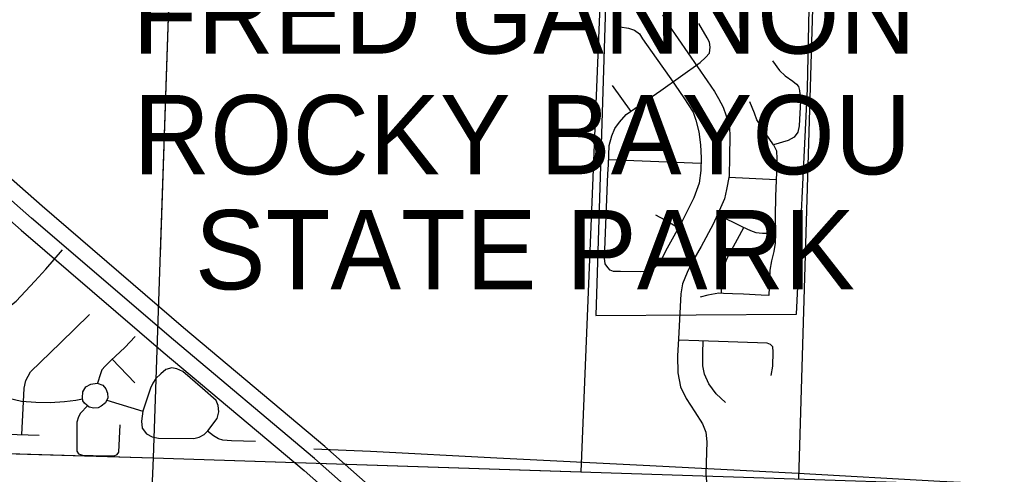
# Model space of a CAD drawing. Extents: x 1219626 to 1426462, y 456797 to 752399.
# Drawn here: x 1360454 to 1366612, y 546709 to 549577 of the extents above; entities that cross this region are included whole.
import ezdxf

# ---------------------------------------------------------------- set-up
doc = ezdxf.new("R2010")
doc.units = 0
for name, color, linetype in [('Local Roads Paved', 7, 'Continuous'), ('Masks', 7, 'Continuous'), ('Masks for Text', 7, 'Continuous'), ('Section Lines', 7, 'Continuous'), ('State Park', 7, 'Continuous'), ('State Park Text', 7, 'Continuous'), ('State Route Divided Highway Outline and Fill', 7, 'Continuous'), ('State Routes Highway Center Lines', 7, 'Continuous')]:
    doc.layers.add(name, color=color, linetype=linetype)

msp = doc.modelspace()

# ---------------------------------------------------------------- linework, layer by layer
at = {"layer": 'Local Roads Paved'}
for p, q in [((1364190.4, 549161), (1364306.7, 548997.8)), ((1364167.5, 548695.3), (1364749.7, 548671.8)), ((1365223.9, 548565.7), (1364925, 548580.7)), ((1361038.4, 547435.6), (1361179.9, 547285.4)), ((1361003.5, 547177.1), (1361232, 547106.8))]:
    msp.add_line(p, q, dxfattribs=at)
for points in [[(1364506.4, 549607.1), (1364545.4, 549542.9), (1364788.1, 549191), (1364834.1, 549124.2), (1364859.2, 549080), (1364888.7, 549024.5), (1364908.6, 548969.9), (1364916.4, 548940.4), (1364928.6, 548892.7), (1364932, 548845), (1364928.6, 548709.8), (1364926.8, 548591), (1364911.2, 548505.2), (1364897.4, 548447.1), (1364872.2, 548389), (1364827.1, 548285.9), (1364750, 548146.3), (1364697.1, 548050.9), (1364662.4, 547981.6), (1364633.8, 547911.4), (1364622.5, 547847.2), (1364607.8, 547563.7), (1364602.6, 547457.1), (1364604.3, 547350.4), (1364619.9, 547260.3), (1364655.5, 547187.5), (1364711, 547104.2), (1364758.7, 547027.1), (1364780.3, 546975.1), (1364787.3, 546915.2), (1364779.5, 546714.1), (1364784.7, 546663)], [(1364239.8, 549530.4), (1364291.8, 549523.4), (1364330, 549510.4), (1364362, 549486.1), (1364381.1, 549454.9), (1364466.9, 549333.6), (1364558.8, 549203.5), (1364642.1, 549083.9), (1364700.1, 548992.9), (1364717.5, 548942.6), (1364735.7, 548869.8), (1364747, 548786.5), (1364750.4, 548705.9), (1364748.7, 548624.4), (1364737.4, 548544.7), (1364704.5, 548452.8), (1364677.6, 548397.3), (1364630.8, 548305.4), (1364536.3, 548134.6), (1364487.7, 548041), (1364453.1, 548006.3), (1364416.6, 547989.8), (1364369.8, 547985.5), (1364243.3, 547988.1), (1364199, 547988.9), (1364177.4, 547997.6), (1364161.8, 548013.2), (1364146.2, 548037.5), (1364141.8, 548072.2), (1364162.6, 548604.5), (1364166.1, 548661.7), (1364171.3, 548783.9), (1364187.8, 548843.7), (1364206, 548890.6), (1364236.3, 548929.6), (1364277.9, 548977.3), (1364359.4, 549035.3), (1364496.4, 549129.8), (1364745.2, 549306.7), (1364779, 549337), (1364802.4, 549365.6), (1364808.5, 549402.1), (1364802.4, 549435), (1364788.6, 549461.9), (1364735.7, 549552.9)], [(1365200.4, 549316.2), (1365244.6, 549256.4), (1365280.1, 549221.7), (1365327.8, 549188.8), (1365352.1, 549169.7), (1365364.2, 549155.8), (1365371.1, 549130.7), (1365377.2, 549063.9), (1365368.5, 548906.2), (1365359.9, 548866.3), (1365337.3, 548835.9), (1365299.2, 548815.1), (1365206.4, 548787.4), (1365156.1, 548860.2), (1365101.5, 548945.2), (1365086.8, 548986.8), (1365057.3, 549058.7)], [(1365206, 548788), (1365226.4, 548749.2), (1365228.1, 548699), (1365226.4, 548614), (1365218.6, 548462.3), (1365217.7, 548337.5), (1365219.4, 548226.5), (1365217.7, 548167.5), (1365208.2, 548115.5), (1365193.4, 548055.7), (1365184.8, 547996.7), (1365182.2, 547940.4), (1365177.8, 547837.2), (1365130.1, 547838.1), (1365017.4, 547845), (1364948.9, 547847.6), (1364891.7, 547850.2), (1364861.4, 547852), (1364792.9, 547839), (1364744.4, 547826)], [(1362310, 546871), (1362666.3, 546856.3), (1363462.2, 546813.8), (1364427.1, 546764.4), (1365361.6, 546716.7), (1366256.3, 546667.3), (1367164.8, 546622.2), (1367542, 546604.9), (1367765.6, 546603.1), (1367974.6, 546610.1), (1368079.5, 546616.2), (1368255.4, 546629.2), (1368565.8, 546674.2), (1368850.2, 546726.3), (1368988.9, 546756.6), (1369250.7, 546826), (1369484.8, 546898.8), (1369633.9, 546949.1), (1369932.1, 547072.2), (1370656.9, 547398.1), (1371339.1, 547704.2), (1372184.4, 548082.1), (1372487, 548217.4), (1372702.8, 548311)], [(1364607.1, 548262.6), (1364523.3, 548312.3), (1364465, 548342.6)], [(1364854.1, 548347.6), (1365010.5, 548269), (1365062.5, 548247.3), (1365096.3, 548235.2), (1365137.1, 548230), (1365219.4, 548230)], [(1364878.4, 547851), (1364880.5, 547937.8), (1364889.1, 547991.5), (1364899.5, 548034), (1364916.9, 548075.6), (1364979.3, 548191.8), (1365020.1, 548265)], [(1359142.5, 546467.9), (1359161.1, 546551.3), (1359165.4, 546658), (1359168, 546723.9), (1359177.5, 546812.3), (1359186.2, 546850.4), (1359207, 546905.9), (1359256.4, 546970.9), (1359396.9, 547106.2), (1359491.4, 547198.1), (1359632.7, 547335.1), (1359704.6, 547405.3), (1359771.4, 547463.4), (1359819.1, 547499.8), (1359891.9, 547546.6), (1360097.4, 547621.1), (1360200.5, 547655), (1360297.6, 547702.6), (1360371.3, 547752.9), (1360432, 547802.3), (1360550.8, 547928), (1360620.1, 548003.5), (1360724.2, 548125.7)], [(1360467.4, 546959.9), (1360476.6, 547125.3), (1360482.9, 547252.5), (1360493.3, 547301), (1360521.9, 547355.6), (1360711.8, 547537.7), (1360893.9, 547716.3)], [(1361183.4, 547579.3), (1361116.7, 547510), (1361030, 547427.6), (1360993.6, 547391.2), (1360973.6, 547368.7), (1360963.2, 547342.6), (1360945, 547283.7)], [(1365191.4, 547333), (1365201.7, 547392.1), (1365205.1, 547482.2), (1365201.7, 547512.6), (1365187.8, 547527.3), (1365167.8, 547536), (1364735.2, 547550.7), (1364607.4, 547556.2)], [(1364904.7, 547161.5), (1364844.5, 547216.9), (1364798.5, 547280.2), (1364771.7, 547340.9), (1364760.4, 547392.9), (1364760.4, 547475.3), (1364763.4, 547549.7)], [(1361640.3, 546982.9), (1361700.1, 547061.8), (1361710.5, 547102.5), (1361706.2, 547142.4), (1361693.2, 547174.5), (1361607.3, 547249.9), (1361483.4, 547358.2), (1361444.4, 547375.6), (1361414, 547379.9), (1361375.9, 547370.4), (1361344.7, 547343.5), (1361313.5, 547314), (1361293.5, 547283.7), (1361278.8, 547252.5), (1361232, 547106.8)], [(1360386, 547190.3), (1360466.7, 547171.2), (1360556.8, 547165.1), (1360647, 547163.4), (1360738, 547167.7), (1360809.1, 547178.1), (1360851.6, 547184.5)], [(1360882, 547141.4), (1360838.4, 547095.6), (1360825.4, 547072.2), (1360815.8, 547037.5), (1360815, 546854.6), (1360825.4, 546838.1), (1360850.5, 546831.2), (1360917.3, 546827.7), (1361049.9, 546826), (1361069, 546835.5), (1361079.4, 546849.4), (1361087.2, 547021)], [(1361232, 547106.8), (1361223.3, 547045.3), (1361227.6, 547001.1), (1361254.5, 546964.7), (1361289.2, 546945.6), (1361329.1, 546937.8), (1361552.7, 546935.2), (1361585.7, 546943.9), (1361617.7, 546961.2), (1361640.3, 546982.9)], [(1360299.4, 547002.2), (1360342.7, 546970.1), (1360369.6, 546963.1), (1360576.8, 546956.2)], [(1361942, 546916.1), (1361789.4, 546921.3), (1361735.6, 546925.6), (1361707.9, 546932.6), (1361676.7, 546951.7), (1361639, 546981.6)]]:
    msp.add_lwpolyline(points, dxfattribs=at)
msp.add_lwpolyline([(1360904.3, 547278.5), (1360942.4, 547284.6), (1360977.9, 547272.4), (1360998.8, 547249), (1361007.4, 547220.4), (1361010, 547192.7), (1360996.2, 547159.7), (1360968.4, 547138.9), (1360948.5, 547128.5), (1360922.5, 547126.8), (1360892.1, 547132.8), (1360863.5, 547157.1), (1360853.1, 547173.6), (1360850.5, 547192.7), (1360853.1, 547229.9), (1360872.2, 547261.2)], close=True, dxfattribs=at)
at = {"layer": 'Masks'}
msp.add_line((1361404.8, 549976.7), (1361340.2, 548094.8), dxfattribs=at)
at = {"layer": 'Masks for Text'}
msp.add_lwpolyline([(1364157.2, 549934), (1364086.3, 547711.9), (1365351.2, 547720.3), (1365422.2, 549140.4), (1365438.9, 549950.7), (1364232.4, 549988.3)], close=True, dxfattribs=at)
at = {"layer": 'Section Lines'}
for p, q in [((1361423.7, 550528.5), (1361296.2, 546813.7)), ((1355893.4, 546972.1), (1361296.2, 546813.7)), ((1361296.2, 546813.7), (1361066.1, 541455.3)), ((1361296.2, 546813.7), (1366686.8, 546636.2))]:
    msp.add_line(p, q, dxfattribs=at)
at = {"layer": 'State Park'}
msp.add_line((1363994.4, 546724.8), (1364162.8, 550879.3), dxfattribs=at)
msp.add_lwpolyline([(1355893.4, 546972.1), (1361296.2, 546813.7), (1363994.4, 546724.8)], dxfattribs=at)
at = {"layer": 'State Route Divided Highway Outline and Fill'}
for points in [[(1358658.1, 549961.1), (1358998.4, 549560.4), (1359317.9, 549254.7), (1359706.6, 548915.2), (1360464.5, 548249.2), (1361358.7, 547480.4), (1362247.2, 546733.7), (1362720.6, 546315.6), (1363146.2, 545949.6), (1363413.8, 545723.6), (1364110.6, 545108.2), (1364949.7, 544386), (1365882.6, 543567.9), (1366132.9, 543352), (1366461.6, 543061)], [(1366594.2, 543210.8), (1366264.5, 543502.6), (1366013.9, 543718.8), (1365080.9, 544536.9), (1364242, 545259), (1363544.6, 545875), (1363275.9, 546101.8), (1362852, 546466.3), (1362377.8, 546885.2), (1361488.2, 547632.8), (1360595.8, 548400.1), (1359838.4, 549065.6), (1359452.9, 549402.4), (1359144.1, 549697.7)]]:
    msp.add_lwpolyline(points, dxfattribs=at)
at = {"layer": 'State Routes Highway Center Lines'}
msp.add_line((1365367, 546679.6), (1365529.7, 552225), dxfattribs=at)
msp.add_lwpolyline([(1366527.9, 543135.9), (1366198.7, 543427.3), (1365948.2, 543643.3), (1365015.3, 544461.4), (1364176.3, 545183.6), (1363479.2, 545799.3), (1363211, 546025.7), (1362786.3, 546391), (1362312.5, 546809.4), (1361423.4, 547556.6), (1360530.1, 548324.6), (1359772.5, 548990.4), (1359385.4, 549328.5), (1359071.3, 549629.1)], dxfattribs=at)

# ---------------------------------------------------------------- texts
at = {"layer": 'State Park Text'}
for s, rotation, p in [('FRED GANNON', 359.99965, (1361165.5, 549362.5)), ('ROCKY BAYOU', 359.99965, (1361172, 548601.2)), ('STATE PARK', 359.99966, (1361558.8, 547875.8))]:
    msp.add_text(s, height=500, rotation=rotation, dxfattribs=at).set_placement(p)

doc.saveas('drawing.dxf')
